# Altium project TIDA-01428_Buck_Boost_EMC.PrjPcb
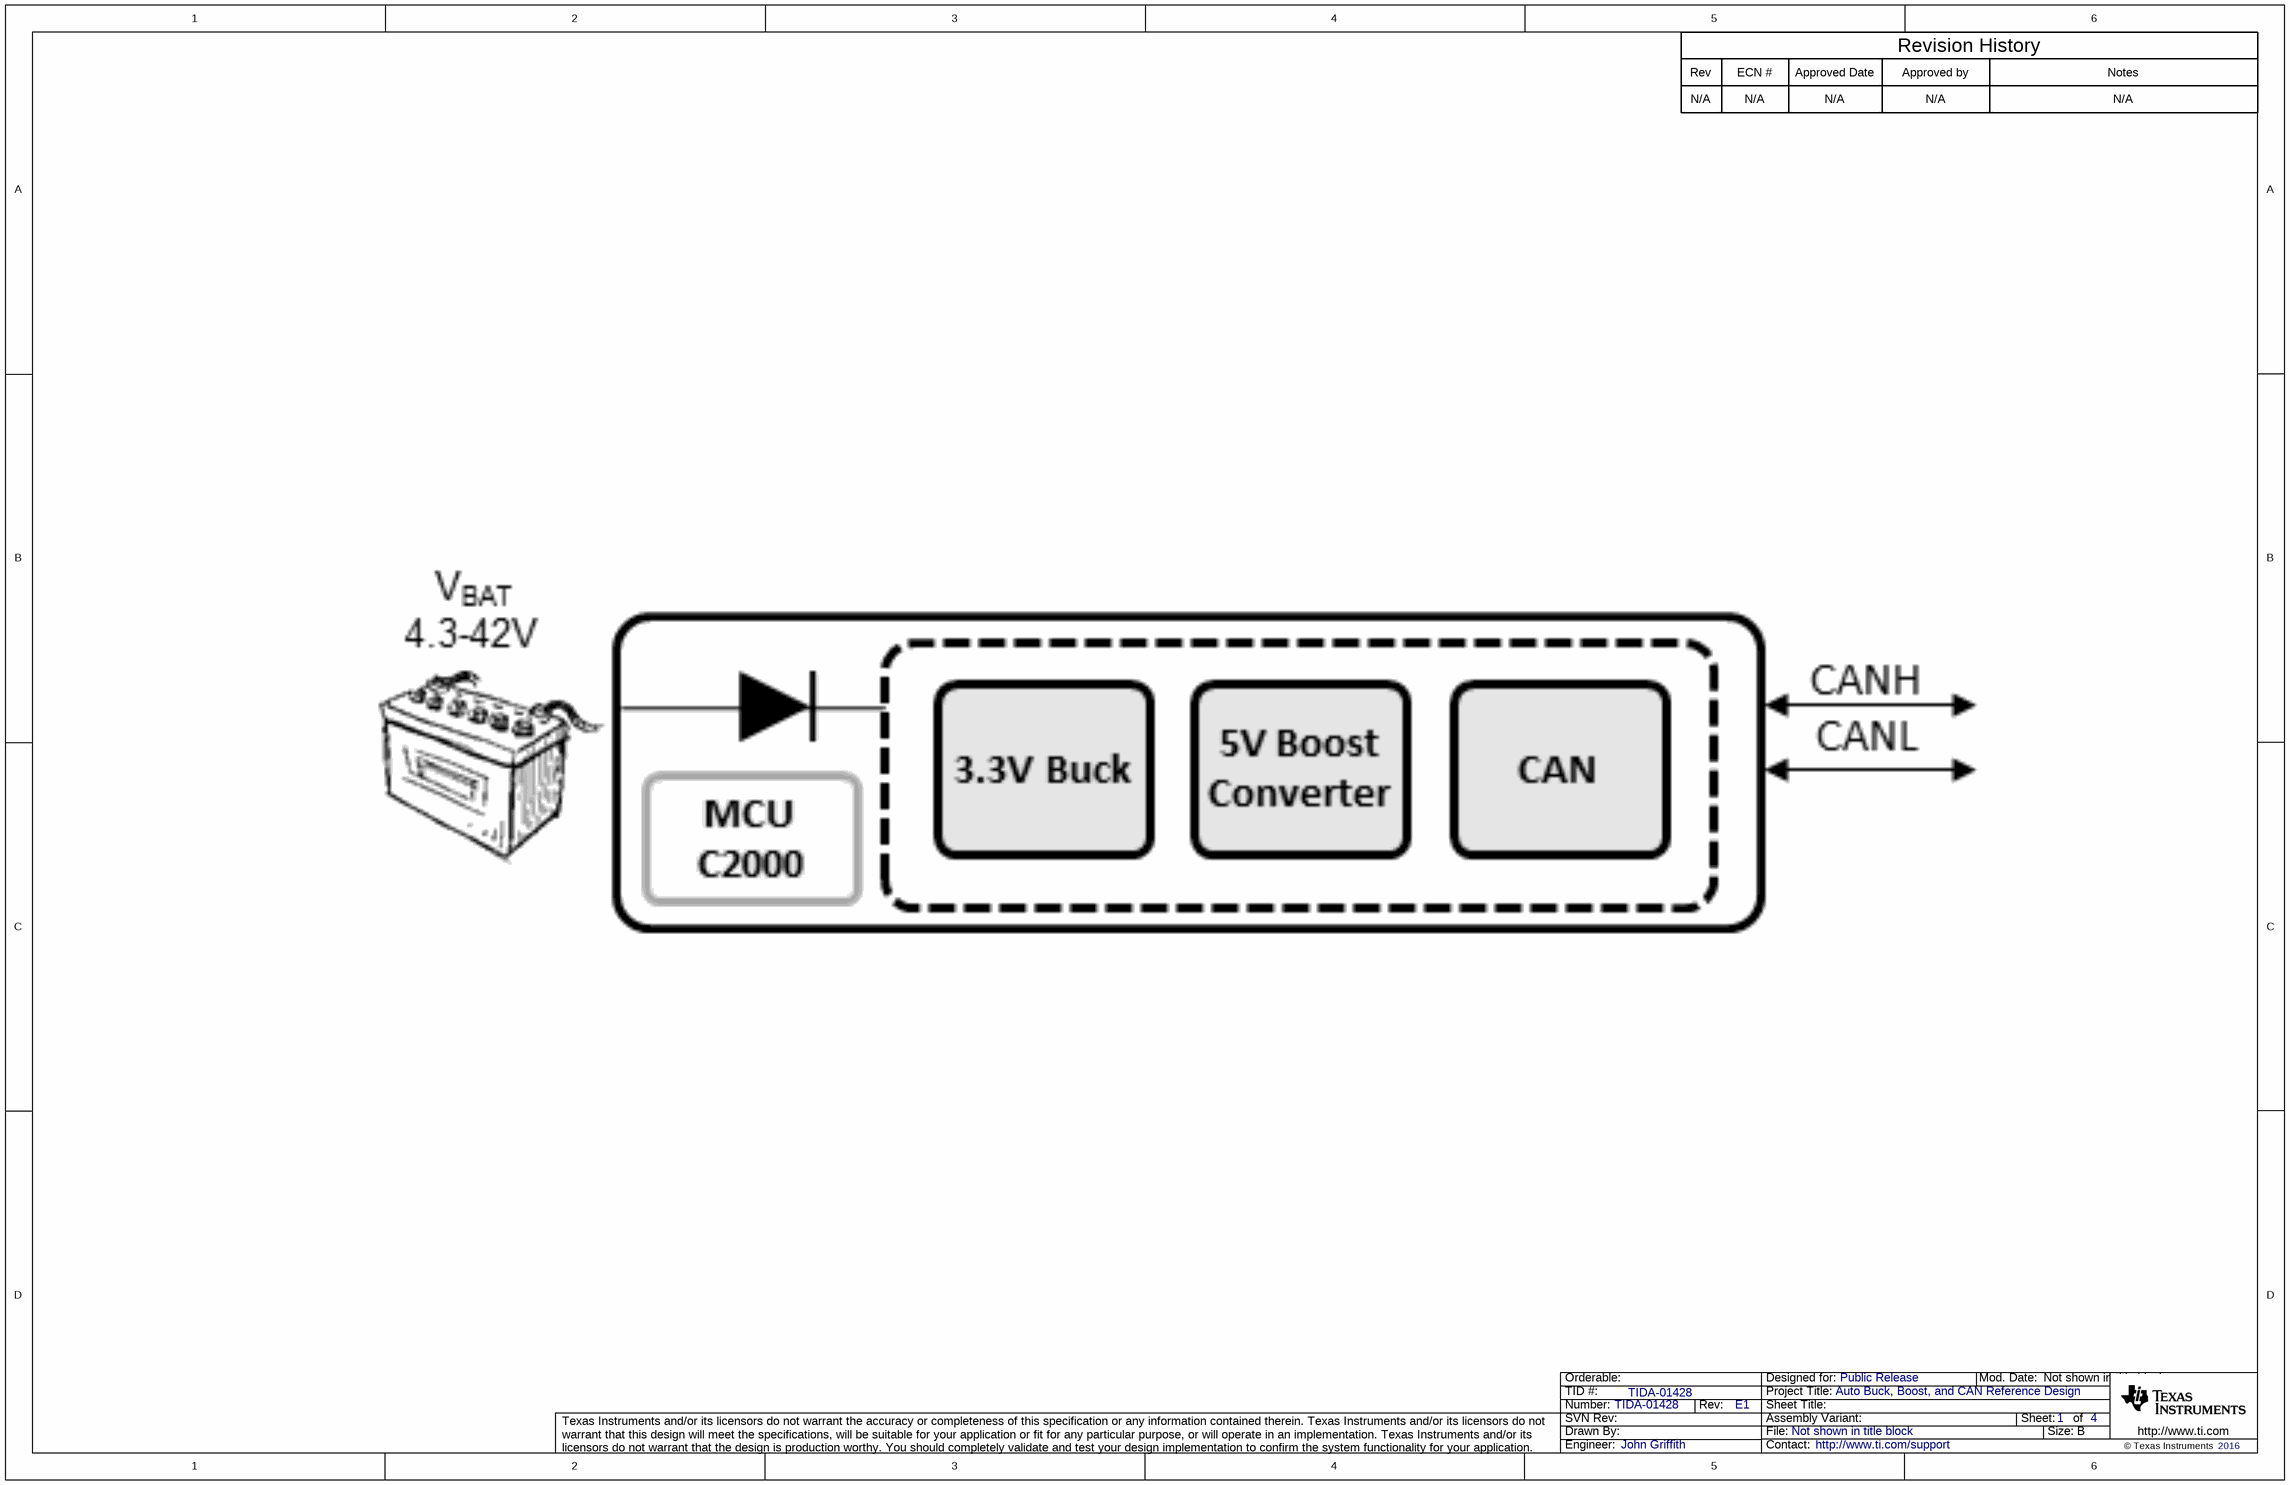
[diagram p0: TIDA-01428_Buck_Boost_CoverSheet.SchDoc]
CopyrightYear: 2016; PCB_Layout: John Griffith; PCB_Rev: E1; PRJ_Customer: Public Release; PRJ_Engineer: John Griffith; PRJ_Number: TIDA-01428; PRJ_Title: Auto Buck, Boost, and CAN Reference Design; SCH_Rev: E1; TechSupport: http://www.ti.com/support; TID: TIDA-01428
4 sheets, 128 parts. Net scope: global (net labels, ports and power ports of the same name join across sheets).
Board file: TIDA-01428_Buck_Boost_PCB.PcbDoc
Sheets:
  TIDA-01428_Buck_Boost_CoverSheet.SchDoc
  TIDA-01428_Buck_Boost_MCU.SchDoc
  TIDA-01428_Buck_Boost_Main.SchDoc
  TIDA-01428_Buck_Boost_Hardware.SchDoc

## Sheet TIDA-01428_Buck_Boost_CoverSheet.SchDoc
size 431 x 279 mm; Date: Not shown in title block; ApprovedBy: Not shown in title block; CheckedBy: Not shown in title block; Author: Not shown in title block; CompanyName: Not shown in title block; Engineer: Not shown in title block; Organization: Not shown in title block; Address1: Not shown in title block; Address2: Not shown in title block; Address3: Not shown in title block; Address4: Not shown in title block; DocumentNumber: 1; Revision: Use project parameter SCH_Rev; SheetNumber: 1; SheetTotal: 4; PageSetup: Record=PageOptions¦CenterHorizontal=True¦CenterVertical=True¦PrintScale=1.00¦XCorrection=1.00¦YCorrection=1.00¦PrintKind=0¦BorderSize=5000000¦LeftOffset=0¦BottomOffset=0¦Orientation=2¦PaperLength=1000¦PaperWidth=1000¦Scale=100¦PaperSource=15¦PrintQuality=600¦MediaType=1¦DitherType=10¦PaperKind=Letter¦PrintScaleMode=1

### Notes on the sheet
- Rev
- N/A
- ECN #
- Approved Date
- Approved by
- Revision History
- Notes

## Sheet TIDA-01428_Buck_Boost_MCU.SchDoc
size 431 x 279 mm; Date: Not shown in title block; ApprovedBy: Not shown in title block; CheckedBy: Not shown in title block; Author: Not shown in title block; CompanyName: Not shown in title block; Engineer: Not shown in title block; Organization: Not shown in title block; Address1: Not shown in title block; Address2: Not shown in title block; Address3: Not shown in title block; Address4: Not shown in title block; DocumentNumber: 2; Revision: Use project parameter SCH_Rev; SheetNumber: 2; SheetTotal: 4; PageSetup: Record=PageOptions¦CenterHorizontal=True¦CenterVertical=True¦PrintScale=1.00¦XCorrection=1.00¦YCorrection=1.00¦PrintKind=0¦BorderSize=5000000¦LeftOffset=0¦BottomOffset=0¦Orientation=2¦PaperLength=1000¦PaperWidth=1000¦Scale=100¦PaperSource=15¦PrintQuality=600¦MediaType=1¦DitherType=10¦PaperKind=Letter¦PrintScaleMode=1
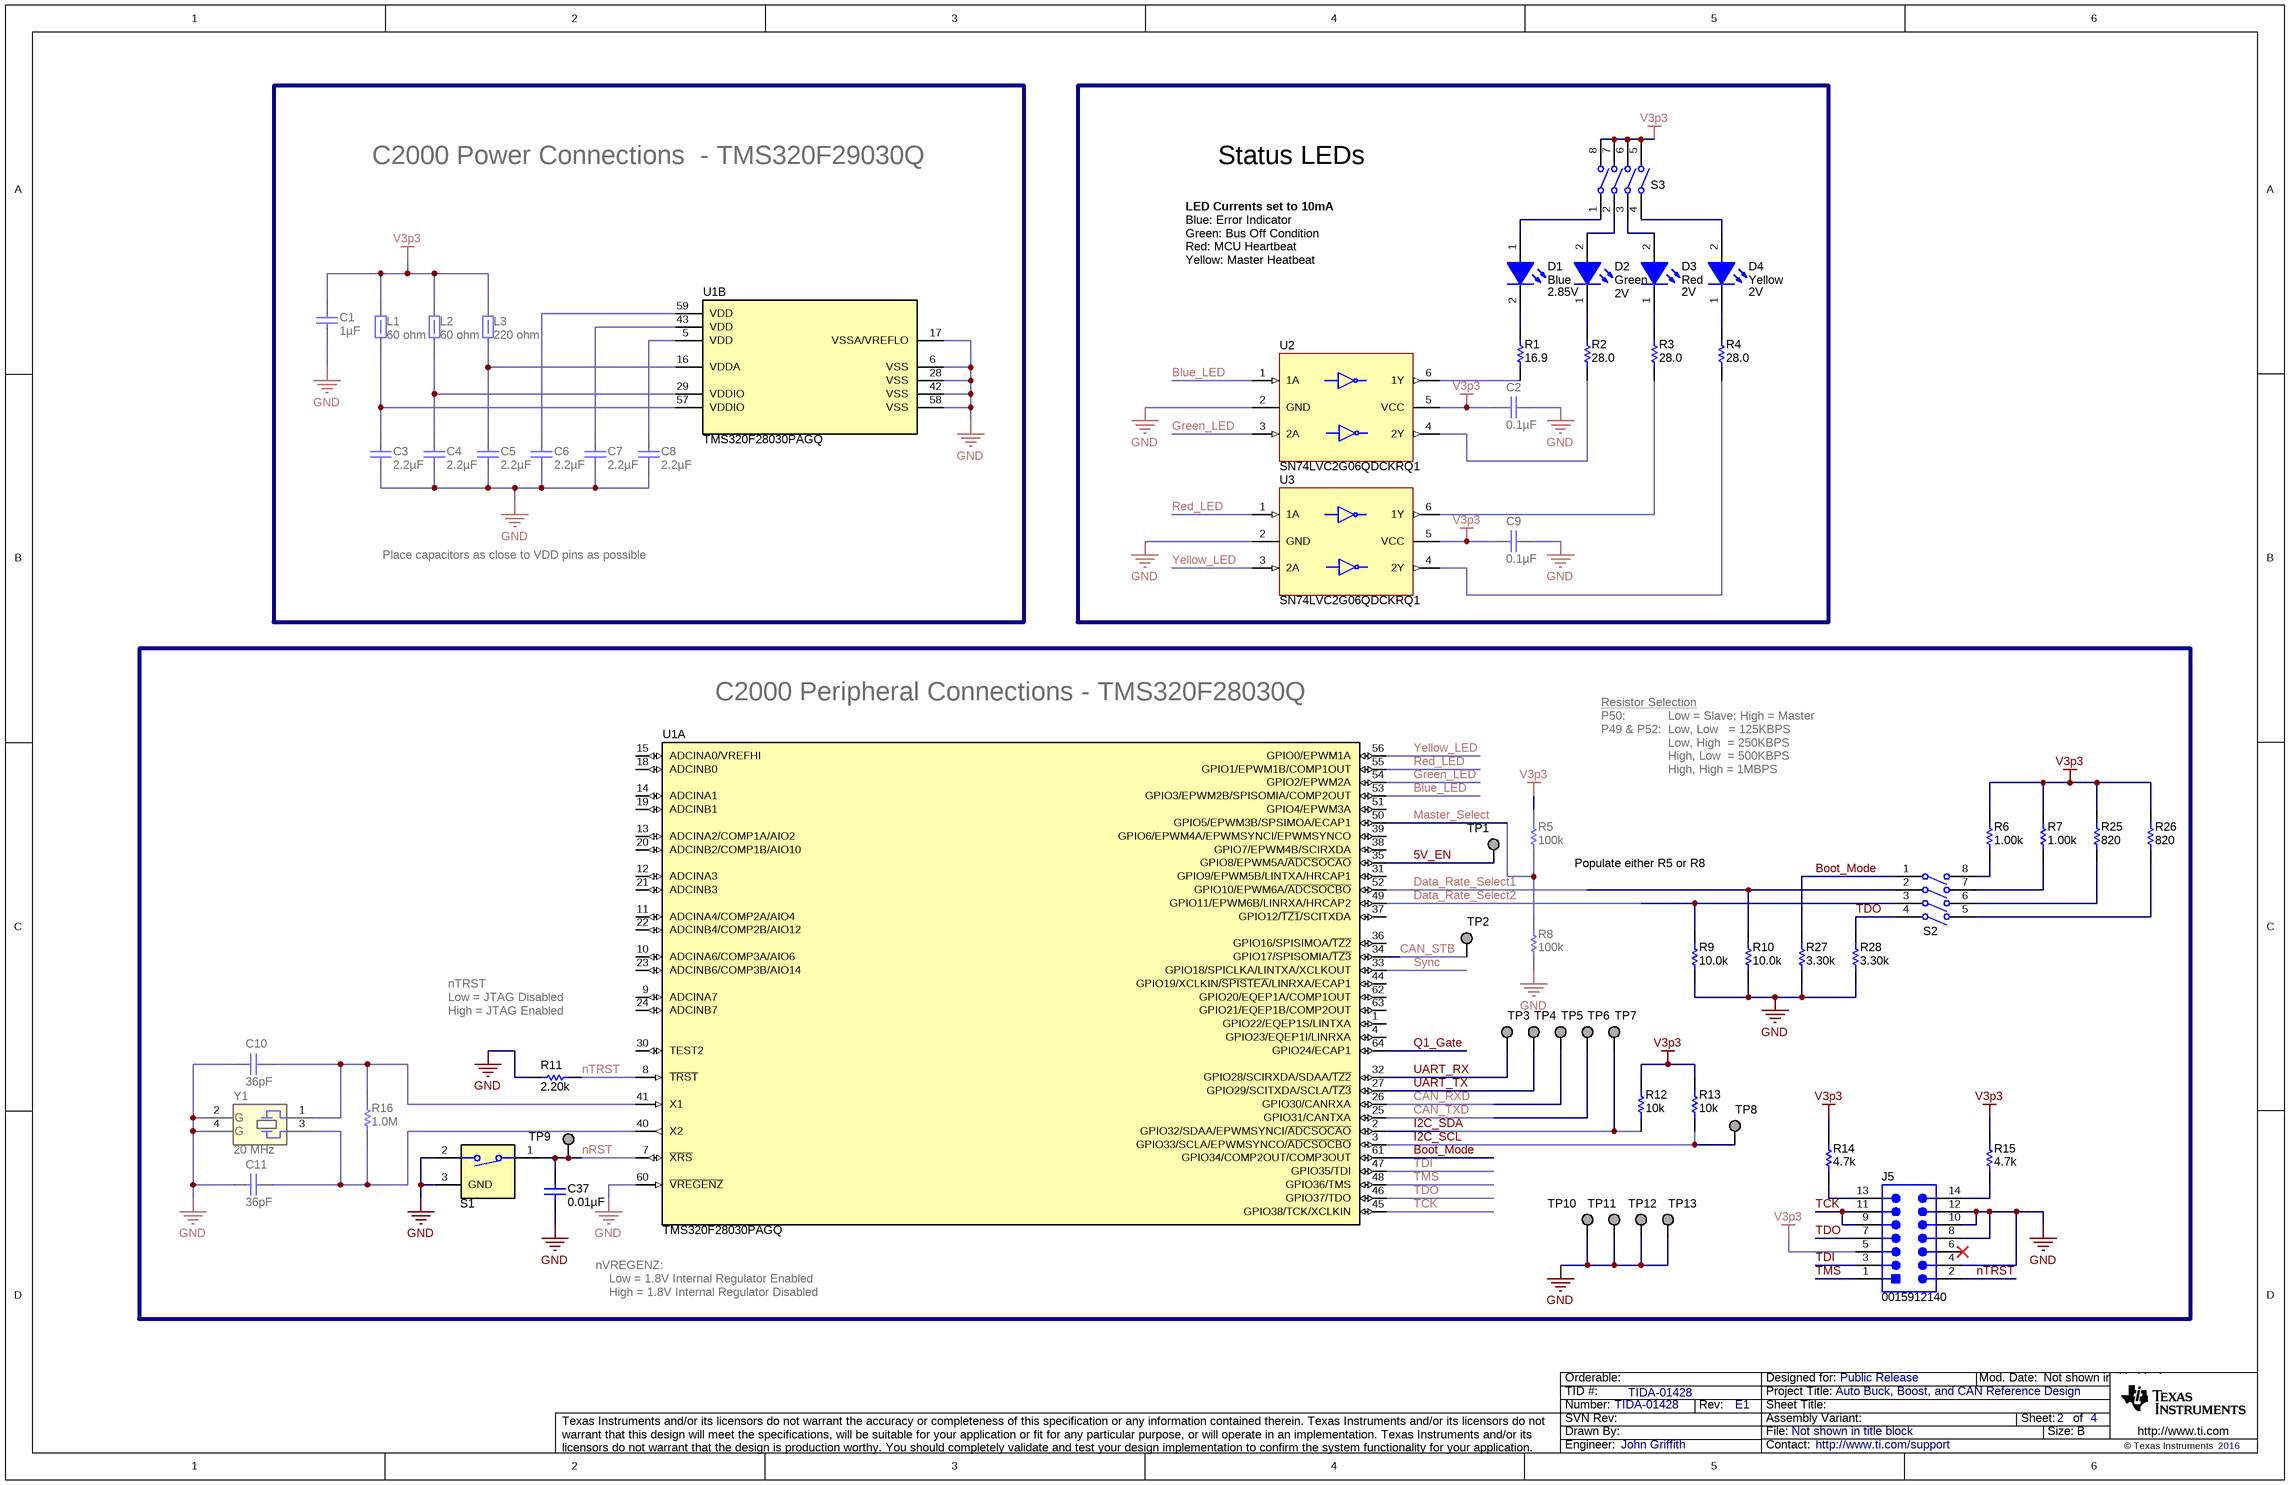
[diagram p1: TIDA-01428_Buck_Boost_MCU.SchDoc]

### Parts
C1  ValueDisplayed: 1µF  [0603S]  (hidden comment: C1608X5R1A105K080AC)
C2  ValueDisplayed: 0.1µF  [0603S]  (hidden comment: 06033C104JAT2A)
C3  ValueDisplayed: 2.2µF  [0603S]  (hidden comment: C0603C225K9PACTU)
C4  ValueDisplayed: 2.2µF  [0603S]  (hidden comment: C0603C225K9PACTU)
C5  ValueDisplayed: 2.2µF  [0603S]  (hidden comment: C0603C225K9PACTU)
C6  ValueDisplayed: 2.2µF  [0603S]  (hidden comment: C0603C225K9PACTU)
C7  ValueDisplayed: 2.2µF  [0603S]  (hidden comment: C0603C225K9PACTU)
C8  ValueDisplayed: 2.2µF  [0603S]  (hidden comment: C0603C225K9PACTU)
C9  ValueDisplayed: 0.1µF  [0603S]  (hidden comment: 06033C104JAT2A)
C10  ValueDisplayed: 36pF  [0402]  (hidden comment: GRM1555C1E360JA01D)
C11  ValueDisplayed: 36pF  [0402]  (hidden comment: GRM1555C1E360JA01D)
C37  ValueDisplayed: 0.01µF  [0603S]  (hidden comment: 06031C103JAT2A)
D1  value Blue  Value2: 2.85V  [LB Q39G_BLUE]  (hidden comment: LB Q39G-L2N2-35-1)
D2  value Green  Value2: 2V  [WL-SMCW_GREEN]  (hidden comment: 150060VS75000)
D3  value Red  Value2: 2V  [WL-SMCW_RED]  (hidden comment: 150060RS75000)
D4  value Yellow  Value2: 2V  [WL-SMCW_YELLOW]  (hidden comment: 150060YS75000)
J5  0015912140  [Molex_0015912140]
L1  ValueDisplayed: 60 ohm  [0603S]  (hidden comment: 742792602)
L2  ValueDisplayed: 60 ohm  [0603S]  (hidden comment: 742792602)
L3  ValueDisplayed: 220 ohm  [0805]  (hidden comment: BLM21PG221SN1D)
R1  ValueDisplayed: 16.9  [0603S]  (hidden comment: RC0603FR-0716R9L)
R2  ValueDisplayed: 28.0  [0603S]  (hidden comment: CRCW060328R0FKEA)
R3  ValueDisplayed: 28.0  [0603S]  (hidden comment: CRCW060328R0FKEA)
R4  ValueDisplayed: 28.0  [0603S]  (hidden comment: CRCW060328R0FKEA)
R5  ValueDisplayed: 100k  [0603S]  (hidden comment: CRCW0603100KFKEA)
R6  ValueDisplayed: 1.00k  [0603S]  (hidden comment: CRCW06031K00FKEA)
R7  ValueDisplayed: 1.00k  [0603S]  (hidden comment: CRCW06031K00FKEA)
R8  ValueDisplayed: 100k  [0603S]  (hidden comment: CRCW0603100KFKEA)
R9  ValueDisplayed: 10.0k  [0603S]  (hidden comment: CRCW060310K0FKEA)
R10  ValueDisplayed: 10.0k  [0603S]  (hidden comment: CRCW060310K0FKEA)
R11  ValueDisplayed: 2.20k  [0603S]  (hidden comment: RC0603FR-072K2L)
R12  ValueDisplayed: 10k  [0603S]  (hidden comment: CRCW060310K0JNEA)
R13  ValueDisplayed: 10k  [0603S]  (hidden comment: CRCW060310K0JNEA)
R14  ValueDisplayed: 4.7k  [0603S]  (hidden comment: CRCW06034K70JNEA)
R15  ValueDisplayed: 4.7k  [0603S]  (hidden comment: CRCW06034K70JNEA)
R16  ValueDisplayed: 1.0M  [0402]  (hidden comment: CRCW04021M00JNED)
R25  ValueDisplayed: 820  [0603S]  (hidden comment: RC0603FR-07820RL)
R26  ValueDisplayed: 820  [0603S]  (hidden comment: RC0603FR-07820RL)
R27  ValueDisplayed: 3.30k  [0603S]  (hidden comment: RC0603FR-073K3L)
R28  ValueDisplayed: 3.30k  [0603S]  (hidden comment: RC0603FR-073K3L)
S1  B3U-1100P  [SW_B3U-1100P]  (value not drawn)
S2  1571983-5  [SW_1571983-5]  (value not drawn)
S3  1571983-5  [SW_1571983-5]  (value not drawn)
TP1  PAD_1MM_SQUARE  [PAD_1MM_SQUARE]  (value not drawn)  (no BOM)
TP2  PAD_1MM_SQUARE  [PAD_1MM_SQUARE]  (value not drawn)  (no BOM)
TP3  PAD_1MM_SQUARE  [PAD_1MM_SQUARE]  (value not drawn)  (no BOM)
TP4  PAD_1MM_SQUARE  [PAD_1MM_SQUARE]  (value not drawn)  (no BOM)
TP5  PAD_1MM_SQUARE  [PAD_1MM_SQUARE]  (value not drawn)  (no BOM)
TP6  PAD_1MM_SQUARE  [PAD_1MM_SQUARE]  (value not drawn)  (no BOM)
TP7  PAD_1MM_SQUARE  [PAD_1MM_SQUARE]  (value not drawn)  (no BOM)
TP8  PAD_1MM_SQUARE  [PAD_1MM_SQUARE]  (value not drawn)  (no BOM)
TP9  PAD_1MM_SQUARE  [PAD_1MM_SQUARE]  (value not drawn)  (no BOM)
TP10  PAD_1MM_SQUARE  [PAD_1MM_SQUARE]  (value not drawn)  (no BOM)
TP11  PAD_1MM_SQUARE  [PAD_1MM_SQUARE]  (value not drawn)  (no BOM)
TP12  PAD_1MM_SQUARE  [PAD_1MM_SQUARE]  (value not drawn)  (no BOM)
TP13  PAD_1MM_SQUARE  [PAD_1MM_SQUARE]  (value not drawn)  (no BOM)
U1  TMS320F28030PAGQ  [PAG0064A_N]  (parts A,B of 2)
U2  SN74LVC2G06QDCKRQ1  [DCK0006A_N]
U3  SN74LVC2G06QDCKRQ1  [DCK0006A_N]
Y1  Frequency: 20 MHz  [ABRACON_ABM3B]  (hidden comment: ABM3B-20.000MHZ-10-1-U-T)

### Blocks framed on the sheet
Place capacitors as close to VDD pins as possible: C1 C3-C8 L1-L3 U1

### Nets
GND: C1.2 C2.2 C3.2 C4.2 C5.2 C6.2 C7.2 C8.2 C9.2 C10.2 C11.2 C37.2 J5.4 J5.8 J5.10 J5.12 R8.1 R9.1 R10.1 R11.1 R27.1 R28.1 S1.2 S1.3(GND) TP10.1 TP11.1 TP12.1 TP13.1 U1.6(VSS) U1.17(VSSA/VREFLO) U1.28(VSS) U1.42(VSS) U1.58(VSS) U1.60(~{VREGENZ}) U2.2(GND) U3.2(GND) Y1.2(GND) Y1.4(GND)
V3p3: C1.1 C2.1 C9.1 J5.5 L1.2 L2.2 L3.2 R5.2 R6.2 R7.2 R12.2 R13.2 R14.2 R15.2 R25.2 R26.2 S3.5(B4) S3.6(B3) S3.7(B2) S3.8(B1) U2.5(VCC) U3.5(VCC)
5V_EN: TP1.1 U1.35(GPIO8/EPWM5A/~{ADCSOCAO})
Blue_LED: U1.53(GPIO3/EPWM2B/SPISOMIA/COMP2OUT) U2.1(1A)
Boot_Mode: R27.2 S2.1(A1) U1.61(GPIO34/COMP2OUT/COMP3OUT)
CAN_RXD: TP5.1 U1.26(GPIO30/CANRXA)
CAN_STB: TP2.1 U1.34(GPIO17/SPISOMIA/~{TZ3})
CAN_TXD: TP6.1 U1.25(GPIO31/CANTXA)
Data_Rate_Select1: R10.2 S2.2(A2) U1.52(GPIO10/EPWM6A/~{ADCSOCBO})
Data_Rate_Select2: R9.2 S2.3(A3) U1.49(GPIO11/EPWM6B/LINRXA/HRCAP2)
Green_LED: U1.54(GPIO2/EPWM2A) U2.3(2A)
I2C_SCL: R13.1 TP8.1 U1.3(GPIO33/SCLA/EPWMSYNCO/~{ADCSOCBO})
I2C_SDA: R12.1 TP7.1 U1.2(GPIO32/SDAA/EPWMSYNCI/~{ADCSOCAO})
Master_Select: R5.1 R8.2 U1.50(GPIO5/EPWM3B/SPSIMOA/ECAP1)
nRST: C37.1 S1.1 TP9.1 U1.7(~{XRS})
nTRST: J5.2 R11.2 U1.8(~{TRST})
Q1_Gate: U1.64(GPIO24/ECAP1)
Red_LED: U1.55(GPIO1/EPWM1B/COMP1OUT) U3.1(1A)
Sync: U1.33(GPIO18/SPICLKA/LINTXA/XCLKOUT)
TCK: J5.9 J5.11 U1.45(GPIO38/TCK/XCLKIN)
TDI: J5.3 U1.47(GPIO35/TDI)
TDO: J5.7 R28.2 S2.4(A4) U1.46(GPIO37/TDO)
TMS: J5.1 U1.48(GPIO36/TMS)
UART_RX: TP3.1 U1.32(GPIO28/SCIRXDA/SDAA/~{TZ2})
UART_TX: TP4.1 U1.27(GPIO29/SCITXDA/SCLA/~{TZ3})
Yellow_LED: U1.56(GPIO0/EPWM1A) U3.3(2A)
NetC3_1: C3.1 L1.1 U1.57(VDDIO)
NetC4_1: C4.1 L2.1 U1.29(VDDIO)
NetC5_1: C5.1 L3.1 U1.16(VDDA)
NetC6_1: C6.1 U1.59(VDD)
NetC7_1: C7.1 U1.43(VDD)
NetC8_1: C8.1 U1.5(VDD)
NetC10_1: C10.1 R16.2 U1.41(X1) Y1.1
NetC11_1: C11.1 R16.1 U1.40(X2) Y1.3
NetD1_1: D1.1(A) S3.1(A1)
NetD1_2: D1.2(K) R1.2
NetD2_1: D2.1(K) R2.2
NetD2_2: D2.2(A) S3.2(A2)
NetD3_1: D3.1(K) R3.2
NetD3_2: D3.2(A) S3.3(A3)
NetD4_1: D4.1(K) R4.2
NetD4_2: D4.2(A) S3.4(A4)
NetJ5_13: J5.13 R14.1
NetJ5_14: J5.14 R15.1
NetR1_1: R1.1 U2.6(1Y)
NetR2_1: R2.1 U2.4(2Y)
NetR3_1: R3.1 U3.6(1Y)
NetR4_1: R4.1 U3.4(2Y)
NetR6_1: R6.1 S2.8(B1)
NetR7_1: R7.1 S2.7(B2)
NetR25_1: R25.1 S2.6(B3)
NetR26_1: R26.1 S2.5(B4)

Not connected (* = marked no-connect by the designer): J5 6*; U1 1(GPIO22/EQEP1S/LINTXA) 4(GPIO23/EQEP1I/LINRXA) 9(ADCINA7) 10(ADCINA6/COMP3A/AIO6) 11(ADCINA4/COMP2A/AIO4) 12(ADCINA3) 13(ADCINA2/COMP1A/AIO2) 14(ADCINA1) 15(ADCINA0/VREFHI) 18(ADCINB0) 19(ADCINB1) 20(ADCINB2/COMP1B/AIO10) 21(ADCINB3) 22(ADCINB4/COMP2B/AIO12) 23(ADCINB6/COMP3B/AIO14) 24(ADCINB7) 30(TEST2) 31(GPIO9/EPWM5B/LINTXA/HRCAP1) 36(GPIO16/SPISIMOA/~{TZ2}) 37(GPIO12/~{TZ1}/SCITXDA) 38(GPIO7/EPWM4B/SCIRXDA) 39(GPIO6/EPWM4A/EPWMSYNCI/EPWMSYNCO) 44(GPIO19/XCLKIN/~{SPISTEA}/LINRXA/ECAP1) 51(GPIO4/EPWM3A) 62(GPIO20/EQEP1A/COMP1OUT) 63(GPIO21/EQEP1B/COMP2OUT)

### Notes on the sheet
- C2000 Power Connections  - TMS320F29030Q
- Status LEDs
- Blue: Error Indicator
- Green: Bus Off Condition
- LED Currents set to 10mA
- Red: MCU Heartbeat
- Yellow: Master Heatbeat
- Mode Selection DIP Switches
- Resistor Selection
- (near U1) C2000 Peripheral Connections - TMS320F28030Q
- P49 & P52:
- P50:
- Low = Slave; High = Master
- Low, Low   = 125KBPS
- Low, High  = 250KBPS
- High, Low  = 500KBPS
- High, High = 1MBPS
- (near R5) Populate either R5 or R8
- Low = JTAG Disabled
- High = JTAG Enabled
- nTRST
- JTAG Interface
- nVREGENZ:
- Low = 1.8V Internal Regulator Enabled
- High = 1.8V Internal Regulator Disabled

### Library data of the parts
C1 = C1608X5R1A105K080AC: CAP, CERM, 1 µF, 10 V, +/- 10%, X5R, 0603; Manufacturer: TDK; Polarized: N; CompType: Capacitor; Value: 1uF; U/M: EA; Cap_F: 0.000001; Tolerance_%: 10; Value1: Unknown; Value2: 10V; TaMin_C: -55; TaMax_C: 85; Cap_Case: 0603; SizeArea_mm2: 1.28; SizeAreaWB_mm2: 4.68; SizeX_mm: 1.6; SizeY_mm: 0.8; SizeZ_mm: 1; AEC Category: Q200
C2 C9 = 06033C104JAT2A: CAP, CERM, 0.1 µF, 25 V, +/- 5%, X7R, 0603; Manufacturer: AVX; Polarized: N; CompType: Capacitor; Value: 0.1uF; U/M: EA; Cap_F: 0.0000001; Tolerance_%: 5; ESR_ohm: 0.05; Value1: 0.05 ohm; VDC_V: 25; Value2: 25V; TaMin_C: -55; TaMax_C: 125; Cap_Case: 0603; SizeArea_mm2: 1.28; SizeAreaWB_mm2: 4.68; SizeX_mm: 1.6; SizeY_mm: 0.8; SizeZ_mm: 1; AEC Category: Q200
C3-C8 = C0603C225K9PACTU: CAP, CERM, 2.2 µF, 6.3 V, +/- 10%, X5R, 0603; Manufacturer: Kemet; Polarized: N; CompType: Capacitor; Value: 2.2uF; U/M: EA; Cap_F: 0.0000022; Tolerance_%: 10; Value1: Unknown; VDC_V: 6.3; Value2: 6.3V; TaMin_C: -55; TaMax_C: 85; Cap_Case: 0603; SizeArea_mm2: 1.28; SizeAreaWB_mm2: 4.68; SizeX_mm: 1.6; SizeY_mm: 0.8; SizeZ_mm: 1; AEC Category: Q200
C10 C11 = GRM1555C1E360JA01D: CAP, CERM, 36 pF, 25 V, +/- 5%, C0G/NP0, 0402; Manufacturer: MuRata; Polarized: N; CompType: Capacitor; Value: 36pF; U/M: EA; Cap_F: 0.000000000036; Tolerance_%: 5; Value1: Unknown; VDC_V: 25; Value2: 25V; TaMin_C: -55; TaMax_C: 125; SizeArea_mm2: 0.5; SizeAreaWB_mm2: 3; SizeX_mm: 1; SizeZ_mm: 0.6; AEC Category: Q200
C37 = 06031C103JAT2A: CAP, CERM, 0.01 µF, 100 V, +/- 5%, X7R, 0603; Manufacturer: AVX; Polarized: N; CompType: Capacitor; Value: 0.01uF; U/M: EA; Cap_F: 0.00000001; Tolerance_%: 5; ESR_ohm: 0.098; Value1: 0.098 ohm; VDC_V: 100; Value2: 100V; TaMin_C: -55; TaMax_C: 125; Cap_Case: 0603; SizeArea_mm2: 1.28; SizeAreaWB_mm2: 4.68; SizeX_mm: 1.6; SizeY_mm: 0.8; SizeZ_mm: 1; AEC Category: Q200
D1 = LB Q39G-L2N2-35-1: LED, Blue, SMD; Manufacturer: OSRAM; Vf_V: 2.85; Io_A: 0.15; Tjmax_C: 95; Value1: W; U/M: EA
D2 = 150060VS75000: LED, Green, SMD; Manufacturer: Wurth Elektronik; Type: AlInGaP; Vf_V: 2; Io_A: 0.02; Value1: W; U/M: EA
D3 = 150060RS75000: LED, Red, SMD; Manufacturer: Wurth Elektronik; Type: AlInGaP; Vf_V: 2; Io_A: 0.03; Vr_V: 5; Tjmax_C: 85; Power_TotalModule: 0.072; Value1: 0.072W; Angle: 140; U/M: EA
D4 = 150060YS75000: LED, Yellow, SMD; Manufacturer: Wurth Elektronik; Type: AlInGaP; Vf_V: 2; Io_A: 0.02; Value1: W; U/M: EA
J5 = 0015912140: Header, 100mil, 7x2, SMT; Manufacturer: Molex; SymbolCreator: a0412235
L1 L2 = 742792602: Ferrite Bead, 60 ohm @ 100 MHz, 3 A, 0603; Manufacturer: Wurth Elektronik; Value: 60 ohm; Imax_A: 3; DCR_ohm: 0.04; Value1: 0.04 ohm; Value2: 3A; SizeAreaWB_mm2: 4.68; SizeArea_mm2: 1.28; SizeX_mm: 1.6; SizeY_mm: 0.8; SizeZ_mm: 1; ZTyp@100MHz_Ohm: 60; Ztyp@1GHz_Ohm: 110.436
L3 = BLM21PG221SN1D: Ferrite Bead, 220 ohm @ 100 MHz, 2 A, 0805; Manufacturer: MuRata; Value: 220 ohm; Imax_A: 2; DCR_ohm: 0.045; Value1: 0.045 ohm; Value2: 2A; SizeAreaWB_mm2: 6.75; SizeArea_mm2: 2.5; SizeY_mm: 1.25; SizeZ_mm: 1.45; ZTyp@100MHz_Ohm: 220
R1 = RC0603FR-0716R9L: RES, 16.9, 1%, 0.1 W, 0603; Manufacturer: Yageo America; CompType: Resistor; Value: 16.9; Value_Code: 16R9; Tolerance_%: 1; Power_W: 0.1; Value2: 0.1W; VDC_V: 150; TempCo: 200 ppm/C; SizeArea_mm2: 1.28; SizeX_mm: 1.6; SizeY_mm: 0.8; EIA_Code: E96; U/M: EA; AEC Category: Q200
R2-R4 = CRCW060328R0FKEA: RES, 28.0, 1%, 0.1 W, 0603; Manufacturer: Vishay-Dale; CompType: Resistor; Value: 28.0; Res_ohm: 28; Value_Code: 28R0; Tolerance_%: 1; Power_W: 0.1; Value2: 0.1W; VDC_V: 75; TempCo: 100 ppm/C; SizeArea_mm2: 1.28; SizeX_mm: 1.6; SizeY_mm: 0.8; EIA_Code: E96; U/M: EA; AEC Category: Q200
R5 R8 = CRCW0603100KFKEA: RES, 100 k, 1%, 0.1 W, 0603; Manufacturer: Vishay-Dale; CompType: Resistor; Value: 100k; Res_ohm: 100000; Tolerance_%: 1; Power_W: 0.1; Value2: 0.1W; VDC_V: 75; TempCo: 100 ppm/C; SizeArea_mm2: 1.28; SizeX_mm: 1.6; SizeY_mm: 0.8; EIA_Code: E96; U/M: EA; AEC Category: Q200
R6 R7 = CRCW06031K00FKEA: RES, 1.00 k, 1%, 0.1 W, 0603; Manufacturer: Vishay-Dale; CompType: Resistor; Value: 1.00k; Res_ohm: 1000; Value_Code: 1k00; Tolerance_%: 1; Power_W: 0.1; Value2: 0.1W; VDC_V: 75; TempCo: 100 ppm/C; SizeArea_mm2: 1.28; SizeX_mm: 1.6; SizeY_mm: 0.8; EIA_Code: E96; U/M: EA; AEC Category: Q200
R9 R10 = CRCW060310K0FKEA: RES, 10.0 k, 1%, 0.1 W, 0603; Manufacturer: Vishay-Dale; CompType: Resistor; Value: 10.0k; Res_ohm: 10000; Value_Code: 10k0; Tolerance_%: 1; Power_W: 0.1; Value2: 0.1W; VDC_V: 75; TempCo: 100 ppm/C; SizeArea_mm2: 1.28; SizeX_mm: 1.6; SizeY_mm: 0.8; EIA_Code: E96; U/M: EA; AEC Category: Q200
R11 = RC0603FR-072K2L: RES, 2.20 k, 1%, 0.1 W, 0603; Manufacturer: Yageo America; CompType: Resistor; Value: 2.20k; Res_ohm: 2200; Value_Code: 2k20; Tolerance_%: 1; Power_W: 0.1; Value2: 0.1W; VDC_V: 150; TempCo: 200 ppm/C; SizeArea_mm2: 1.28; SizeX_mm: 1.6; SizeY_mm: 0.8; U/M: EA; AEC Category: Q200
R12 R13 = CRCW060310K0JNEA: RES, 10 k, 5%, 0.1 W, 0603; Manufacturer: Vishay-Dale; CompType: Resistor; Value: 10k; Res_ohm: 10000; Value_Code: 10k0; Tolerance_%: 5; Power_W: 0.1; Value2: 0.1W; VDC_V: 75; TempCo: 200 ppm/C; SizeArea_mm2: 1.28; SizeX_mm: 1.6; SizeY_mm: 0.8; SizeZ_mm: 1; EIA_Code: E24; U/M: EA; AEC Category: Q200
R14 R15 = CRCW06034K70JNEA: RES, 4.7 k, 5%, 0.1 W, 0603; Manufacturer: Vishay-Dale; CompType: Resistor; Value: 4.7k; Res_ohm: 4700; Value_Code: 4k70; Tolerance_%: 5; Power_W: 0.1; Value2: 0.1W; VDC_V: 75; TempCo: 200 ppm/C; SizeArea_mm2: 1.28; SizeX_mm: 1.6; SizeY_mm: 0.8; SizeZ_mm: 1; EIA_Code: E24; U/M: EA; AEC Category: Q200
R16 = CRCW04021M00JNED: RES, 1.0 M, 5%, 0.063 W, 0402; Manufacturer: Vishay-Dale; CompType: Resistor; Value: 1.0Meg; Res_ohm: 1000000; Value_Code: 1M00; Tolerance_%: 5; Power_W: 0.063; Value2: 0.063W; VDC_V: 50; TempCo: 200 ppm/C; SizeArea_mm2: 0.5; SizeX_mm: 1; SizeZ_mm: 0.6; EIA_Code: E24; U/M: EA; AEC Category: Q200
R25 R26 = RC0603FR-07820RL: RES, 820, 1%, 0.1 W, 0603; Manufacturer: Yageo America; CompType: Resistor; Value: 820; Value_Code: 820R; Tolerance_%: 1; Power_W: 0.1; Value2: 0.1W; VDC_V: 150; TempCo: 200 ppm/C; SizeArea_mm2: 1.28; SizeX_mm: 1.6; SizeY_mm: 0.8; U/M: EA; AEC Category: Q200
R27 R28 = RC0603FR-073K3L: RES, 3.30 k, 1%, 0.1 W, 0603; Manufacturer: Yageo America; CompType: Resistor; Value: 3.30k; Res_ohm: 3300; Value_Code: 3k30; Tolerance_%: 1; Power_W: 0.1; Value2: 0.1W; VDC_V: 150; TempCo: 200 ppm/C; SizeArea_mm2: 1.28; SizeX_mm: 1.6; SizeY_mm: 0.8; U/M: EA; AEC Category: Q200
S1 = B3U-1100P: Switch, SPST-NO, Off-Mom, 12 V, SMD; Manufacturer: Omron Electronic Components; SymbolCreator: Altium; VDC_V: 12; PositionCount: 1; CurrentRating_mA: 50
S2 S3 = 1571983-5: Switch, SPST, 4 Pos, Top Actuated, SMD; Manufacturer: TE Connectivity; SymbolCreator: a0412235; VDC_V: 24; PositionCount: 4; CurrentRating_mA: 25
TP1-TP13 = PAD_1MM_SQUARE: 1.0x1.0mm pad, square, SMD; Manufacturer: Any
U1 = TMS320F28030PAGQ: Piccolo Microcontroller, PAG0064A (TQFP-64); Manufacturer: Texas Instruments; SymbolCreator: a0412235; SizeArea_mm2: 144; SizeAreaWB_mm2: 196; SizeX_mm: 12; SizeZ_mm: 1.2; CompType: IC; U/M: EA
U2 U3 = SN74LVC2G06QDCKRQ1: Dual Inverter Buffer/Driver with Open-Drain Output, DCK0006A (SOT-6); Manufacturer: Texas Instruments; SymbolCreator: x0208326; SizeArea_mm2: 4.2; SizeAreaWB_mm2: 9.3; SizeX_mm: 2.1; SizeY_mm: 2; SizeZ_mm: 1.1; CompType: IC; U/M: EA
Y1 = ABM3B-20.000MHZ-10-1-U-T: Crystal, 20 MHz, 10 pF, SMD; Manufacturer: Abracon Corporation; SymbolCreator: a0412235; U/M: EA; TaMin_C: -10; TaMax_C: 60; Frequency Stability: ±10ppm

## Sheet TIDA-01428_Buck_Boost_Main.SchDoc
size 431 x 279 mm; Date: Not shown in title block; ApprovedBy: Not shown in title block; CheckedBy: Not shown in title block; Author: Not shown in title block; CompanyName: Not shown in title block; Engineer: Not shown in title block; Organization: Not shown in title block; Address1: Not shown in title block; Address2: Not shown in title block; Address3: Not shown in title block; Address4: Not shown in title block; DocumentNumber: 3; Revision: Use project parameter SCH_Rev; SheetNumber: 3; SheetTotal: 4; PageSetup: Record=PageOptions¦CenterHorizontal=True¦CenterVertical=True¦PrintScale=1.00¦XCorrection=1.00¦YCorrection=1.00¦PrintKind=0¦BorderSize=5000000¦LeftOffset=0¦BottomOffset=0¦Orientation=2¦PaperLength=1000¦PaperWidth=1000¦Scale=100¦PaperSource=15¦PrintQuality=600¦MediaType=1¦DitherType=10¦PaperKind=Letter¦PrintScaleMode=1
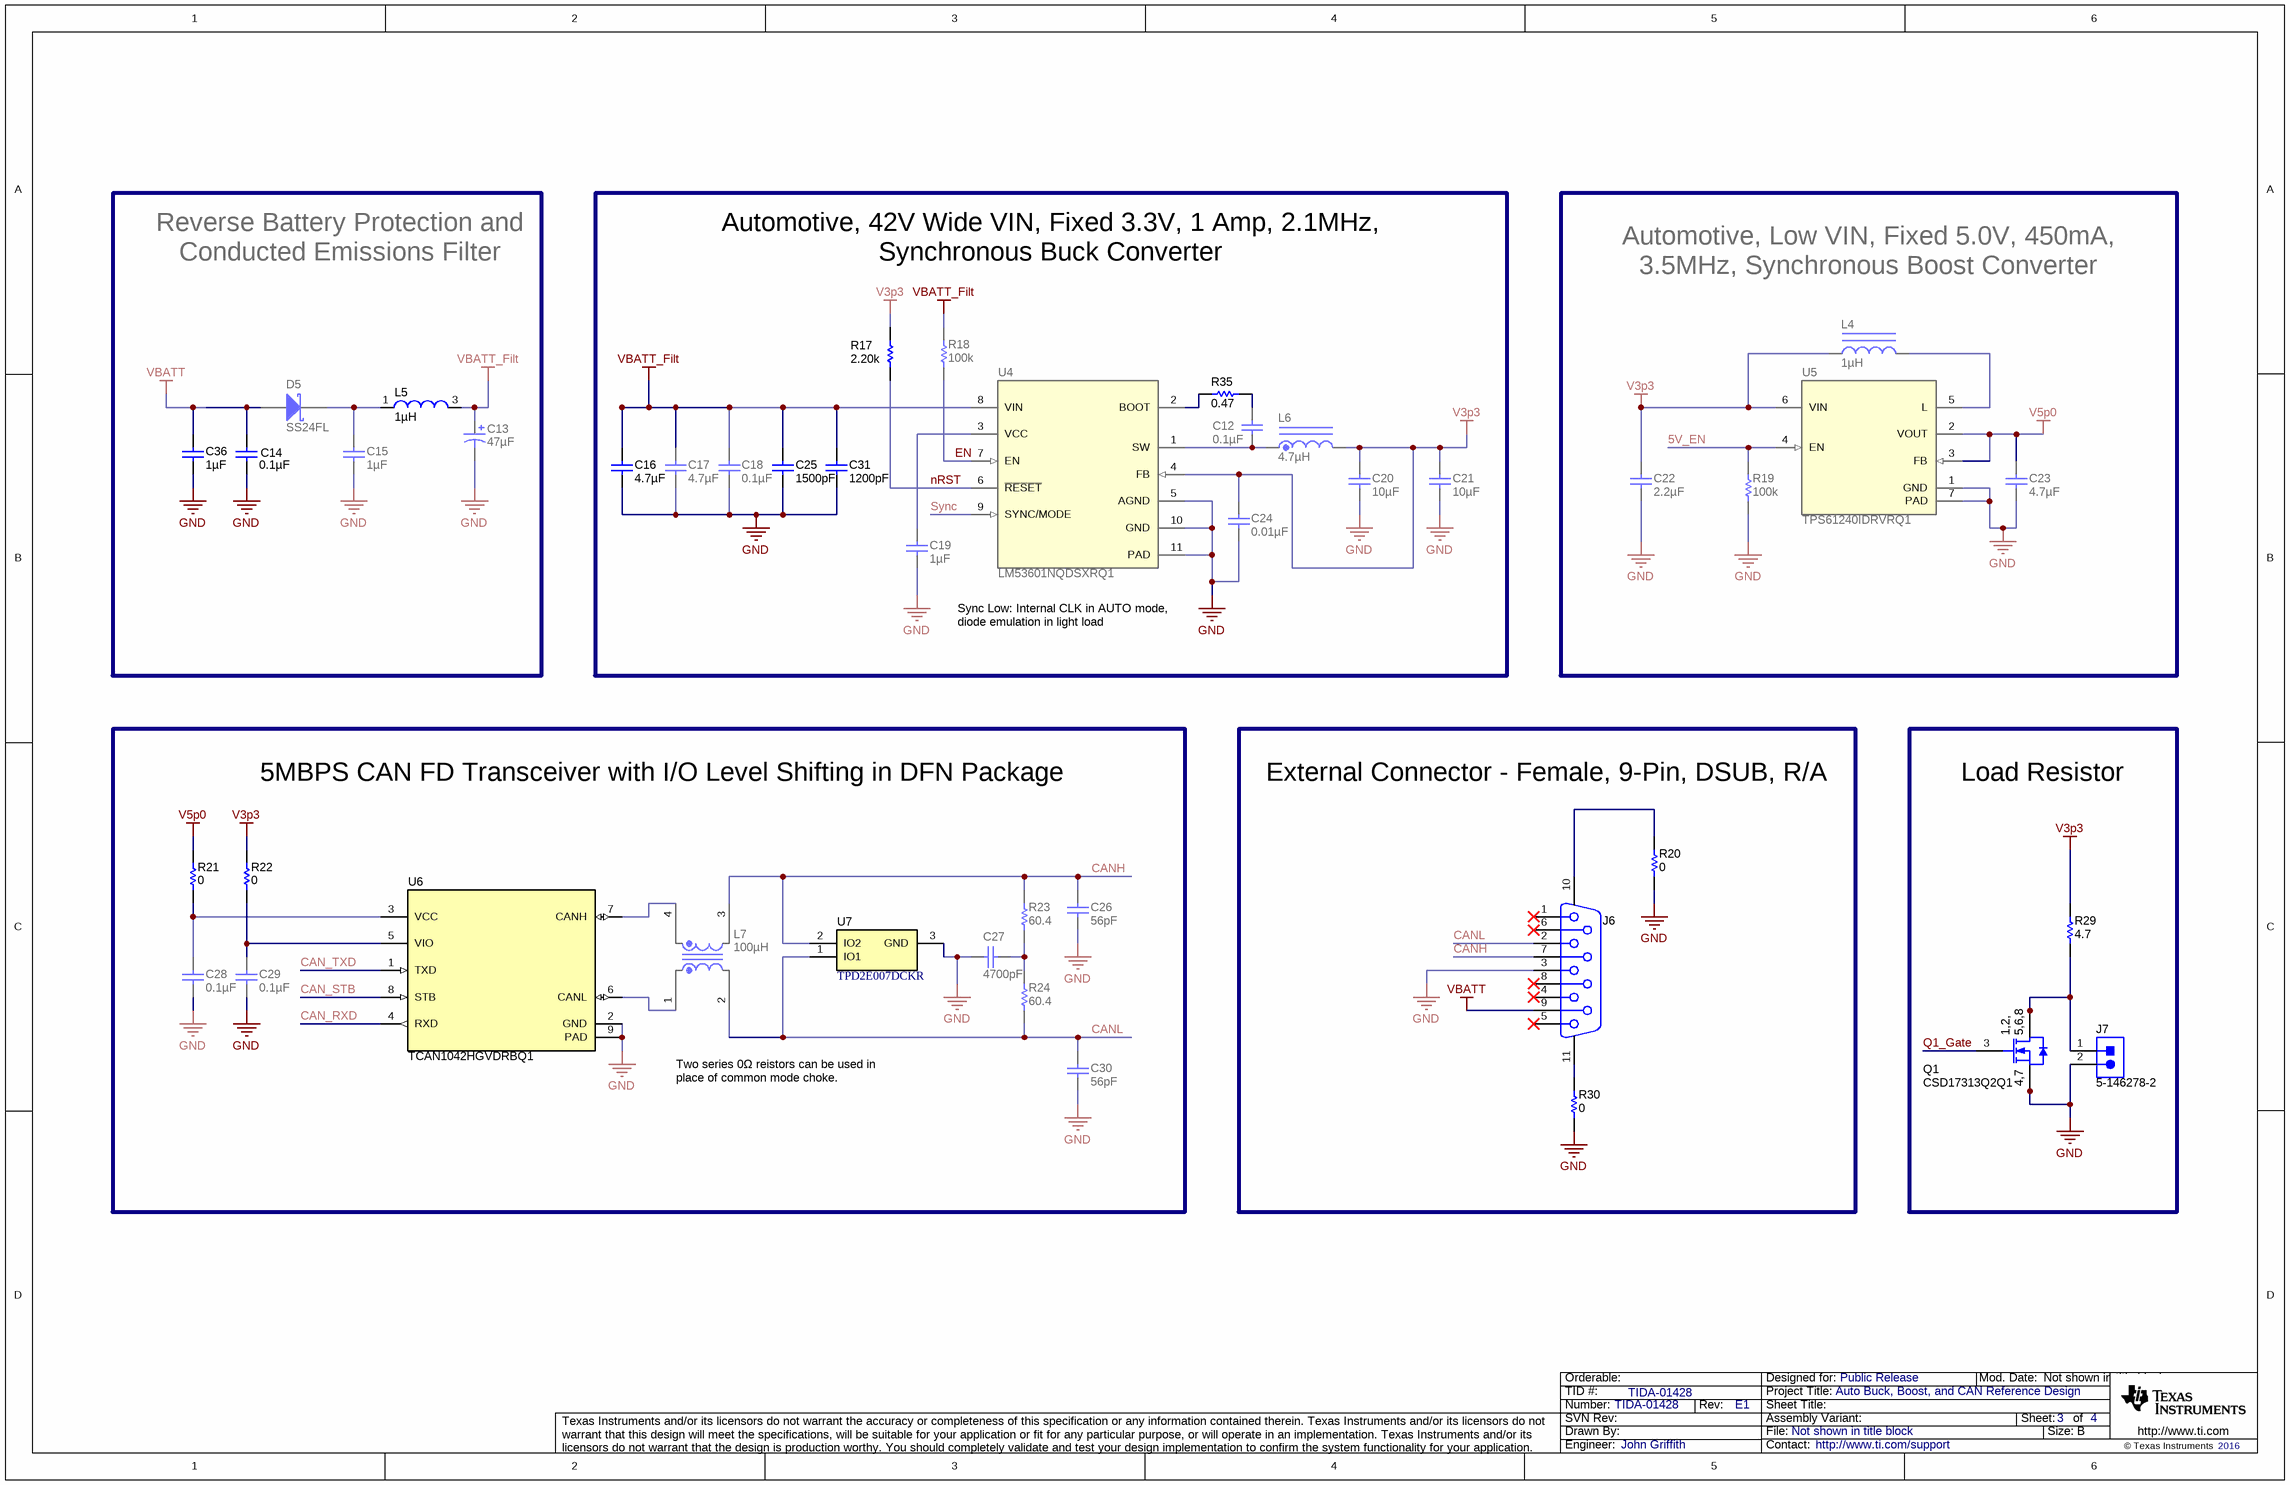
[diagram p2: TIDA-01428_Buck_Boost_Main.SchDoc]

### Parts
C12  ValueDisplayed: 0.1µF  [0603S]  (hidden comment: GCM188R71H104KA57D)
C13  ValueDisplayed: 47µF  [SM_RADIAL_F]  (hidden comment: EEE-FK1J470P)
C14  ValueDisplayed: 0.1µF  [0603S]  (hidden comment: GCJ188R72A104KA01D)
C15  ValueDisplayed: 1µF  [0603]  (hidden comment: GRM188R61H105KAALD)
C16  ValueDisplayed: 4.7µF  [1206_180]  (hidden comment: GRM31CR71H475KA12L)
C17  ValueDisplayed: 4.7µF  [1206_180]  (hidden comment: GRM31CR71H475KA12L)
C18  ValueDisplayed: 0.1µF  [0805_HV]  (hidden comment: C2012X7R2A104K125AA)
C19  ValueDisplayed: 1µF  [0603S]  (hidden comment: GCM188R71C105KA64D)
C20  ValueDisplayed: 10µF  [1206_180]  (hidden comment: GRM31CR71C106KAC7L)
C21  ValueDisplayed: 10µF  [1206_180]  (hidden comment: GRM31CR71C106KAC7L)
C22  ValueDisplayed: 2.2µF  [0603S]  (hidden comment: C0603C225K8PACTU)
C23  ValueDisplayed: 4.7µF  [0603S]  (hidden comment: C0603C475K8PACTU)
C24  ValueDisplayed: 0.01µF  [0402S]  (hidden comment: C1005X7R1C103K050BA)
C25  ValueDisplayed: 1500pF  [0402S]  (hidden comment: CGA2B3X7S2A152K050BB)
C26  ValueDisplayed: 56pF  [0603S]  (hidden comment: GRM1885C1H560JA01D)
C27  ValueDisplayed: 4700pF  [0603S]  (hidden comment: GCM188R71H472KA37D)
C28  ValueDisplayed: 0.1µF  [0603S]  (hidden comment: 06033C104JAT2A)
C29  ValueDisplayed: 0.1µF  [0603S]  (hidden comment: 06033C104JAT2A)
C30  ValueDisplayed: 56pF  [0603S]  (hidden comment: GRM1885C1H560JA01D)
C31  ValueDisplayed: 1200pF  [0402S]  (hidden comment: C0402C122J5GACTU)
C36  ValueDisplayed: 1µF  [0603S]  (hidden comment: UMK107AB7105KA-T)
D5  SS24FL  [SOD-123F]
J6  1734354-1  [TE_1734354-1]  (value not drawn)
J7  5-146278-2  [TE_5-146278-2]
L4  ValueDisplayed: 1µH  [NLCV32]  (hidden comment: NLCV32T-1R0M-PF)
L5  ValueDisplayed: 1µH  [WE-TPC-8015]  (hidden comment: 7440690010)
L6  ValueDisplayed: 4.7µH  [MPI4040R3]  (hidden comment: MPI4040R3-4R7-R)
L7  ValueDisplayed: 100µH  [SIMDAD_1812]  (hidden comment: B82789C0104H001)
Q1  CSD17313Q2Q1  [DQK0006C]
R17  ValueDisplayed: 2.20k  [0603S]  (hidden comment: RC0603FR-072K2L)
R18  ValueDisplayed: 100k  [0603S]  (hidden comment: CRCW0603100KFKEA)
R19  ValueDisplayed: 100k  [0603S]  (hidden comment: CRCW0603100KFKEA)
R20  ValueDisplayed: 0  [0603S]  (hidden comment: ERJ-3GEY0R00V)
R21  ValueDisplayed: 0  [0603S]  (hidden comment: ERJ-3GEY0R00V)
R22  ValueDisplayed: 0  [0603S]  (hidden comment: ERJ-3GEY0R00V)
R23  ValueDisplayed: 60.4  [1206]  (hidden comment: CRCW120660R4FKEA)
R24  ValueDisplayed: 60.4  [1206]  (hidden comment: CRCW120660R4FKEA)
R29  ValueDisplayed: 4.7  [PNP300]  (hidden comment: PNP300JR-73-4R7)
R30  ValueDisplayed: 0  [0603S]  (hidden comment: ERJ-3GEY0R00V)
R35  ValueDisplayed: 0.47  [0402S]  (hidden comment: ERJ-2BQFR47X)
U4  LM53601NQDSXRQ1  [DSX0010A]
U5  TPS61240IDRVRQ1  [DRV0006A]
U6  TCAN1042HGVDRBQ1  [DRB0008F]
U7  TPD2E007DCKR  [DCK0003A_N]

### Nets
GND: C13.2(-) C14.2 C15.2 C16.2 C17.2 C18.2 C19.2 C20.2 C21.2 C22.2 C23.2 C24.2 C25.2 C26.2 C27.2 C28.2 C29.2 C30.2 C31.2 C36.2 J6.3 J7.2 Q1.4(S) Q1.7(S) R19.1 R20.2 R30.2 U4.5(AGND) U4.10(GND) U4.11(PAD) U5.1(GND) U5.7(PAD) U6.2(GND) U6.9(PAD) U7.3(GND)
V3p3: C20.1 C21.1 C22.1 C24.1 L4.1 L6.2 R17.1 R22.1 R29.2 U4.4(FB) U5.6(VIN)
V5p0: C23.1 R21.1 U5.2(VOUT) U5.3(FB)
VBATT: C14.1 C36.1 D5.2(A) J6.9
VBATT_Filt: C13.1(+) C16.1 C17.1 C18.1 C25.1 C31.1 L5.3 R18.2 U4.8(VIN)
5V_EN: R19.2 U5.4(EN)
CAN_RXD: U6.4(RXD)
CAN_STB: U6.8(STB)
CAN_TXD: U6.1(TXD)
CANH: C26.1 J6.7 L7.3 R23.2 U7.2(IO2)
CANL: C30.1 J6.2 L7.2 R24.1 U7.1(IO1)
EN: R18.1 U4.7(EN)
nRST: R17.2 U4.6(~{RESET})
Q1_Gate: Q1.3(G)
Sync: U4.9(SYNC/MODE)
NetC12_1: C12.1 R35.2
NetC12_2: C12.2 L6.1 U4.1(SW)
NetC15_1: C15.1 D5.1(K) L5.1
NetC19_1: C19.1 U4.3(VCC)
NetC27_1: C27.1 R23.1 R24.2
NetC28_1: C28.1 R21.2 U6.3(VCC)
NetC29_1: C29.1 R22.2 U6.5(VIO)
NetJ6_10: J6.10 R20.1
NetJ6_11: J6.11 R30.1
NetJ7_1: J7.1 Q1.1(D) Q1.2(D) Q1.5(D) Q1.6(D) Q1.8(D) R29.1
NetL4_2: L4.2 U5.5(L)
NetL7_1: L7.1 U6.6(CANL)
NetL7_4: L7.4 U6.7(CANH)
NetR35_1: R35.1 U4.2(BOOT)

Not connected (* = marked no-connect by the designer): J6 1* 4* 5* 6* 8*

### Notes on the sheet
- Reverse Battery Protection and Conducted Emissions Filter
- Automotive, 42V Wide VIN, Fixed 3.3V, 1 Amp, 2.1MHz, Synchronous Buck Converter
- Automotive, Low VIN, Fixed 5.0V, 450mA, 3.5MHz, Synchronous Boost Converter
- diode emulation in light load
- Sync Low: Internal CLK in AUTO mode,
- 5MBPS CAN FD Transceiver with I/O Level Shifting in DFN Package
- External Connector - Female, 9-Pin, DSUB, R/A
- Load Resistor
- Two series 0Ω reistors can be used in
- place of common mode choke.

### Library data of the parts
C12 = GCM188R71H104KA57D: CAP, CERM, 0.1 µF, 50 V, +/- 10%, X7R, 0603; Manufacturer: MuRata; Polarized: N; CompType: Capacitor; Value: 0.1uF; U/M: EA; Cap_F: 0.0000001; Tolerance_%: 10; ESR_ohm: 0.02; Value1: 0.02 ohm; VDC_V: 50; Value2: 50V; IRMS_A: 1.84; TaMin_C: -55; TaMax_C: 125; Cap_Case: 0603; SizeArea_mm2: 1.28; SizeAreaWB_mm2: 4.68; SizeX_mm: 1.6; SizeY_mm: 0.8; SizeZ_mm: 1; AEC Category: Q200
C13 = EEE-FK1J470P: CAP, AL, 47 µF, 63 V, +/- 20%, 0.65 ohm, AEC-Q200 Grade 2, SMD; Manufacturer: Panasonic; Polarized: Y; CompType: Capacitor; Value: 47uF; U/M: EA; Cap_F: 0.000047; Tolerance_%: 20; VDC_V: 63; Value2: 63V; ESR_ohm: 0.65; IRMS_A: 0.25; TaMin_C: -55; TaMax_C: 105; Cap_Case: F; SizeAreaWB_mm2: 123.6; SizeArea_mm2: 83; SizeX_mm: 10; SizeY_mm: 8.3; SizeZ_mm: 10.2; AEC Category: Q200; AEC Grade: 2
C14 = GCJ188R72A104KA01D: CAP, CERM, 0.1 µF, 100 V, +/- 10%, X7R, AEC-Q200 Grade 1, 0603; Manufacturer: MuRata; Polarized: N; CompType: Capacitor; Value: 0.1uF; U/M: EA; Cap_F: 0.0000001; Tolerance_%: 10; Value1: Unknown; VDC_V: 100; Value2: 100V; TaMin_C: -55; TaMax_C: 125; Cap_Case: 0603; SizeArea_mm2: 1.28; SizeAreaWB_mm2: 4.68; SizeX_mm: 1.6; SizeY_mm: 0.8; SizeZ_mm: 1; AEC Category: Q200; AEC Qualified: Y
C15 = GRM188R61H105KAALD: CAP, CERM, 1 µF, 50 V, +/- 10%, X5R, 0603; Manufacturer: MuRata; Polarized: N; CompType: Capacitor; Value: 1uF; U/M: EA; Cap_F: 0.000001; Tolerance_%: 10; Value1: Unknown; VDC_V: 50; Value2: 50V; TaMin_C: -55; TaMax_C: 85; SizeArea_mm2: 1.28; SizeAreaWB_mm2: 4.68; SizeX_mm: 1.6; SizeY_mm: 0.8; SizeZ_mm: 1; AEC Category: Q200
C16 C17 = GRM31CR71H475KA12L: CAP, CERM, 4.7 µF, 50 V, +/- 10%, X7R, 1206; Manufacturer: MuRata; Polarized: N; CompType: Capacitor; Value: 4.7uF; U/M: EA; Cap_F: 0.0000047; Tolerance_%: 10; Value1: Unknown; VDC_V: 50; Value2: 50V; TaMin_C: -55; TaMax_C: 125; Cap_Case: 2220; SizeArea_mm2: 5.12; SizeAreaWB_mm2: 10.92; SizeX_mm: 3.2; SizeY_mm: 1.6; SizeZ_mm: 1.8; AEC Category: Q200
C18 = C2012X7R2A104K125AA: CAP, CERM, 0.1 µF, 100 V, +/- 10%, X7R, 0805; Manufacturer: TDK; Polarized: N; CompType: Capacitor; Value: 0.1uF; U/M: EA; Cap_F: 0.0000001; Tolerance_%: 10; ESR_ohm: 0.020726; Value1: 0.020726 ohm; VDC_V: 100; Value2: 100V; IRMS_A: 1.456; TaMin_C: -55; TaMax_C: 125; Cap_Case: 0805; SizeArea_mm2: 2.5; SizeAreaWB_mm2: 6.75; SizeX_mm: 2; SizeY_mm: 1.25; SizeZ_mm: 1.45; AEC Category: Q200
C19 = GCM188R71C105KA64D: CAP, CERM, 1 µF, 16 V, +/- 10%, X7R, AEC-Q200 Grade 1, 0603; Manufacturer: MuRata; Polarized: N; CompType: Capacitor; Value: 1uF; U/M: EA; Cap_F: 0.000001; Tolerance_%: 10; Value1: Unknown; VDC_V: 16; Value2: 16V; TaMin_C: -55; TaMax_C: 125; Cap_Case: 0603; SizeArea_mm2: 1.28; SizeAreaWB_mm2: 4.68; SizeX_mm: 1.6; SizeY_mm: 0.8; SizeZ_mm: 1; AEC Category: Q200; AEC Qualified: Y
C20 C21 = GRM31CR71C106KAC7L: CAP, CERM, 10 µF, 16 V, +/- 10%, X7R, 1206; Manufacturer: MuRata; Polarized: N; CompType: Capacitor; Value: 10uF; U/M: EA; Cap_F: 0.00001; Tolerance_%: 10; Value1: Unknown; VDC_V: 16; Value2: 16V; TaMin_C: -55; TaMax_C: 125; Cap_Case: 1206; SizeArea_mm2: 5.12; SizeAreaWB_mm2: 10.92; SizeX_mm: 3.2; SizeY_mm: 1.6; SizeZ_mm: 1.8; AEC Category: Q200
C22 = C0603C225K8PACTU: CAP, CERM, 2.2 µF, 10 V, +/- 10%, X5R, 0603; Manufacturer: Kemet; Polarized: N; CompType: Capacitor; Value: 2.2uF; U/M: EA; Cap_F: 0.0000022; Tolerance_%: 10; Value1: Unknown; Value2: 10V; TaMin_C: -55; TaMax_C: 85; Cap_Case: 0603; SizeArea_mm2: 1.28; SizeAreaWB_mm2: 4.68; SizeX_mm: 1.6; SizeY_mm: 0.8; SizeZ_mm: 1; AEC Category: Q200
C23 = C0603C475K8PACTU: CAP, CERM, 4.7 µF, 10 V, +/- 10%, X5R, 0603; Manufacturer: Kemet; Polarized: N; CompType: Capacitor; Value: 4.7uF; U/M: EA; Cap_F: 0.0000047; Tolerance_%: 10; ESR_ohm: 0.006; Value1: 0.006 ohm; Value2: 10V; IRMS_A: 7.24; TaMin_C: -55; TaMax_C: 85; Cap_Case: 0603; SizeArea_mm2: 1.28; SizeAreaWB_mm2: 4.68; SizeX_mm: 1.6; SizeY_mm: 0.8; SizeZ_mm: 1; AEC Category: Q200
C24 = C1005X7R1C103K050BA: CAP, CERM, 0.01 µF, 16 V, +/- 10%, X7R, 0402; Manufacturer: TDK; Polarized: N; CompType: Capacitor; Value: 0.01uF; U/M: EA; Cap_F: 0.00000001; Tolerance_%: 10; ESR_ohm: 0.0623; Value1: 0.0623 ohm; VDC_V: 16; Value2: 16V; TaMin_C: -55; TaMax_C: 125; Cap_Case: 0402; SizeArea_mm2: 0.5; SizeAreaWB_mm2: 3; SizeX_mm: 1; SizeZ_mm: 0.6; AEC Category: Q200
C25 = CGA2B3X7S2A152K050BB: CAP, CERM, 1500 pF, 100 V, +/- 10%, X7S, AEC-Q200 Grade 1, 0402; Manufacturer: TDK; Polarized: N; CompType: Capacitor; Value: 1500pF; U/M: EA; Cap_F: 0.0000000015; Tolerance_%: 10; ESR_ohm: 1.89793; Value1: 1.89793 ohm; VDC_V: 100; Value2: 100V; IRMS_A: 0.24508; TaMin_C: -55; TaMax_C: 125; Cap_Case: 0402; SizeArea_mm2: 0.5; SizeAreaWB_mm2: 3; SizeX_mm: 1; SizeZ_mm: 0.6; AEC Category: Q200; AEC Qualified: Y
C26 C30 = GRM1885C1H560JA01D: CAP, CERM, 56 pF, 50 V, +/- 5%, C0G/NP0, 0603; Manufacturer: MuRata; Polarized: N; CompType: Capacitor; Value: 56pF; U/M: EA; Cap_F: 0.000000000056; Tolerance_%: 5; Value1: Unknown; VDC_V: 50; Value2: 50V; TaMin_C: -55; TaMax_C: 125; Cap_Case: 0603; SizeArea_mm2: 1.28; SizeAreaWB_mm2: 4.68; SizeX_mm: 1.6; SizeY_mm: 0.8; SizeZ_mm: 1; AEC Category: Q200
C27 = GCM188R71H472KA37D: CAP, CERM, 4700 pF, 50 V, +/- 10%, X7R, AEC-Q200 Grade 1, 0603; Manufacturer: MuRata; Polarized: N; CompType: Capacitor; Value: 4700pF; U/M: EA; Cap_F: 0.0000000047; Tolerance_%: 10; Value1: Unknown; VDC_V: 50; Value2: 50V; TaMin_C: -55; TaMax_C: 125; Cap_Case: 0603; SizeArea_mm2: 1.28; SizeAreaWB_mm2: 4.68; SizeX_mm: 1.6; SizeY_mm: 0.8; SizeZ_mm: 1; AEC Category: Q200; AEC Qualified: Y
C28 C29 = 06033C104JAT2A: as C2 on sheet TIDA-01428_Buck_Boost_MCU
C31 = C0402C122J5GACTU: CAP, CERM, 1200 pF, 50 V, +/- 5%, C0G/NP0, 0402; Manufacturer: Kemet; Polarized: N; CompType: Capacitor; Value: 1200pF; U/M: EA; Cap_F: 0.0000000012; Tolerance_%: 5; Value1: Unknown; VDC_V: 50; Value2: 50V; TaMin_C: -55; TaMax_C: 125; Cap_Case: 0402; SizeArea_mm2: 0.5; SizeAreaWB_mm2: 3; SizeX_mm: 1; SizeZ_mm: 0.6; AEC Category: Q200; Green_Lifecycle: Not Set; Green_REACh: Incomplete
C36 = UMK107AB7105KA-T: CAP, CERM, 1 µF, 50 V, +/- 10%, X7R, 0603; Manufacturer: Taiyo Yuden; Polarized: N; CompType: Capacitor; Value: 1uF; U/M: EA; Cap_F: 0.000001; Tolerance_%: 10; Value1: Unknown; VDC_V: 50; Value2: 50V; TaMin_C: -55; TaMax_C: 125; Cap_Case: 0603; SizeArea_mm2: 1.28; SizeAreaWB_mm2: 4.68; SizeX_mm: 1.6; SizeY_mm: 0.8; SizeZ_mm: 1; AEC Category: Q200
D5 = SS24FL: Diode, Schottky, 40 V, 2 A, AEC-Q101, SOD-123F; Manufacturer: Fairchild Semiconductor; U/M: EA; Vf_V: 0.55; Value: 40V; Value1: 2A; Value2: 0.55V; Io_A: 2; Vr_V: 40; TJmax_C: 125; SizeAreaWB_mm2: 11.7; SizeArea_mm2: 5.6; SizeX_mm: 3.5; SizeY_mm: 1.6; SizeZ_mm: 1.1; AEC Category: Q101; AEC Qualified: Y
J6 = 1734354-1: Receptacle, D-Sub, 9 Position, R/A, TH; Manufacturer: TE Connectivity; SymbolCreator: Altium; Gender: Female; ContactFinish: Gold
J7 = 5-146278-2: Header, 100mil, 2x1, Tin, TH; Manufacturer: TE Connectivity; SymbolCreator: a0412235
L4 = NLCV32T-1R0M-PF: Inductor, Wirewound, Ferrite, 1 µH, 1 A, 0.06 ohm, SMD; Manufacturer: TDK; Value: 1uH; Ind_H: 1.0E-6; Imax_A: 1; Irms: 1A @ 20C rise; Isat: 1A @ 10% inductance drop; DCR_ohm: 0.06; Value2: 1A; SizeAreaWB_mm2: 13.44; SizeArea_mm2: 7.04; SizeX_mm: 3.2; SizeY_mm: 2.2; SizeZ_mm: 2.5; AEC Category: Q200
L5 = 7440690010: Inductor, Shielded Drum Core, Ferrite, 1 µH, 3.6 A, 0.026 ohm, SMD; Manufacturer: Wurth Elektronik; SymbolCreator: a0411947; Ind_H: 1.0E-6; Value: 1uH; Imax_A: 3.6; Irms: 3.6A @ 40C rise; Isat: 3.8A @ 35% inductance drop; DCR_ohm: 0.026; Value2: 3.6A; SizeAreaWB_mm2: 100; SizeArea_mm2: 64; SizeX_mm: 8; SizeZ_mm: 1.35; AEC Category: Q200
L6 = MPI4040R3-4R7-R: Inductor, Shielded, 4.7 µH, 2.3 A, 0.092 ohm, SMD; Manufacturer: Coiltronics; Value: 4.7uH; SymbolCreator: a0412235; Ind_H: 4.7E-6; Imax_A: 2.3; Irms: 2.3A @ 40C rise; Isat: 4.8A @ 30% inductance drop; DCR_ohm: 0.092; Value2: 2.3A; SizeAreaWB_mm2: 27.577; SizeArea_mm2: 18.067; SizeX_mm: 4.45; SizeY_mm: 4.06; SizeZ_mm: 1.8; AEC Category: Q200
L7 = B82789C0104H001: Coupled inductor, 100 µH, 0.15 A, 1.5 ohm, SMD; Manufacturer: TDK; SymbolCreator: a0412235; Value: 100uH; Ind_H: 100.0E-6; DCR_ohm: 1.5
Q1 = CSD17313Q2Q1: MOSFET, N-CH, 30 V, 5 A, AEC-Q101, DQK0006C (WSON-6); Manufacturer: Texas Instruments; Alternate Manufacturer: None; U/M: EA; ChType: N; Value: 30V; VdsMax_V: 30; Value1: 0.032 ohm; Rdson45_ohm: 0.032; Value2: 2.1 nC; QgTyp_nC: 2.1; Vgs_V: 10; IdsMax_A: 5; SizeAreaWB_mm2: 9; SizeArea_mm2: 4; SizeX_mm: 2; SizeZ_mm: 0.8; AEC Category: Q101; AEC Qualified: Y
R17 = RC0603FR-072K2L: as R11 on sheet TIDA-01428_Buck_Boost_MCU
R18 R19 = CRCW0603100KFKEA: as R5 on sheet TIDA-01428_Buck_Boost_MCU
R20-R22 R30 = ERJ-3GEY0R00V: RES, 0, 5%, 0.1 W, 0603; Manufacturer: Panasonic; CompType: Resistor; Value: 0; Value_Code: 0000; Tolerance_%: 5; Power_W: 0.1; Value2: 0.1W; VDC_V: 50; TempCo: 600 ppm/C; SizeArea_mm2: 1.28; SizeX_mm: 1.6; SizeY_mm: 0.8; SizeZ_mm: 1; EIA_Code: E24; U/M: EA; AEC Category: Q200
R23 R24 = CRCW120660R4FKEA: RES, 60.4, 1%, 0.25 W, 1206; Manufacturer: Vishay-Dale; CompType: Resistor; Value: 60.4; Value_Code: 60R4; Tolerance_%: 1; Power_W: 0.25; Value2: 0.25W; VDC_V: 200; TempCo: 100 ppm/C; SizeArea_mm2: 5.12; SizeX_mm: 3.2; SizeY_mm: 1.6; SizeZ_mm: 1.35; EIA_Code: E96; U/M: EA; AEC Category: Q200
R29 = PNP300JR-73-4R7: RES, 4.7, 5%, 3 W, 3W Axial resistor; Manufacturer: Yageo America; Value: 4.7; Value_Code: 4R70; Tolerance_%: 5; Power_W: 3; TempCo: 300 ppm/C; EIA_Code: E24; U/M: EA; AEC Category: Q200; AEC Qualified: N
R35 = ERJ-2BQFR47X: RES, 0.47, 1%, 0.125 W, 0402; Manufacturer: Panasonic; CompType: Resistor; Value: 0.47; Value_Code: R470; Tolerance_%: 1; Power_W: 0.125; Value2: 0.125W; TempCo: 250 ppm/C; SizeArea_mm2: 0.5; SizeZ_mm: 0.6; EIA_Code: E96; U/M: EA; AEC Category: Q200
U4 = LM53601NQDSXRQ1: 3.5V to 36V, 1A Synchronous 2.1MHz Step-Down Converter for Automotive Applications, DSX0010A (WSON-10); Manufacturer: Texas Instruments; SymbolCreator: Altium; SizeArea_mm2: 9; SizeAreaWB_mm2: 16; SizeX_mm: 3; SizeZ_mm: 0.8; CompType: IC; U/M: EA
U5 = TPS61240IDRVRQ1: Automotive Catalog 5V, 400mA, 4MHz Step-Up DC/DC Converter, DRV0006A (WSON-6); Manufacturer: Texas Instruments; SymbolCreator: a799628; SizeArea_mm2: 4; SizeAreaWB_mm2: 9; SizeX_mm: 2; SizeZ_mm: 0.8; CompType: IC; U/M: EA
U6 = TCAN1042HGVDRBQ1: Automotive Fault Protected CAN Transceiver With Flexible Data-Rate, DRB0008F (VSON-8); Manufacturer: Texas Instruments; SymbolCreator: a0411947; SizeArea_mm2: 9; SizeAreaWB_mm2: 16; SizeX_mm: 3; SizeZ_mm: 1; CompType: IC; U/M: EA
U7 = TPD2E007DCKR: ESD Protection Array for AC Signal Data Interface, 2 Channels, -40 to +85 degC, 3-pin SC70 (DCK), Green (RoHS & no Sb/Br); Manufacturer: Texas Instruments; Alternate PartNumber: Equivalent; Breakdown Voltage(Min)(V): +/-14; IEC 61000-4-2 Air-Gap(+/- kV): 15; IEC 61000-4-2 Contact(+/- kV): 8; IO Leakage Current(nA): 50; SubFamily: ESD Solution

## Sheet TIDA-01428_Buck_Boost_Hardware.SchDoc
size 431 x 279 mm; Date: Not shown in title block; ApprovedBy: Not shown in title block; CheckedBy: Not shown in title block; Author: Not shown in title block; CompanyName: Not shown in title block; Engineer: Not shown in title block; Organization: Not shown in title block; Address1: Not shown in title block; Address2: Not shown in title block; Address3: Not shown in title block; Address4: Not shown in title block; DocumentNumber: 4; Revision: Use project parameter SCH_Rev; SheetNumber: 4; SheetTotal: 4; PageSetup: Record=PageOptions¦CenterHorizontal=True¦CenterVertical=True¦PrintScale=1.00¦XCorrection=1.00¦YCorrection=1.00¦PrintKind=0¦BorderSize=5000000¦LeftOffset=0¦BottomOffset=0¦Orientation=2¦PaperLength=1000¦PaperWidth=1000¦Scale=100¦PaperSource=15¦PrintQuality=600¦MediaType=1¦DitherType=10¦PaperKind=Letter¦PrintScaleMode=1
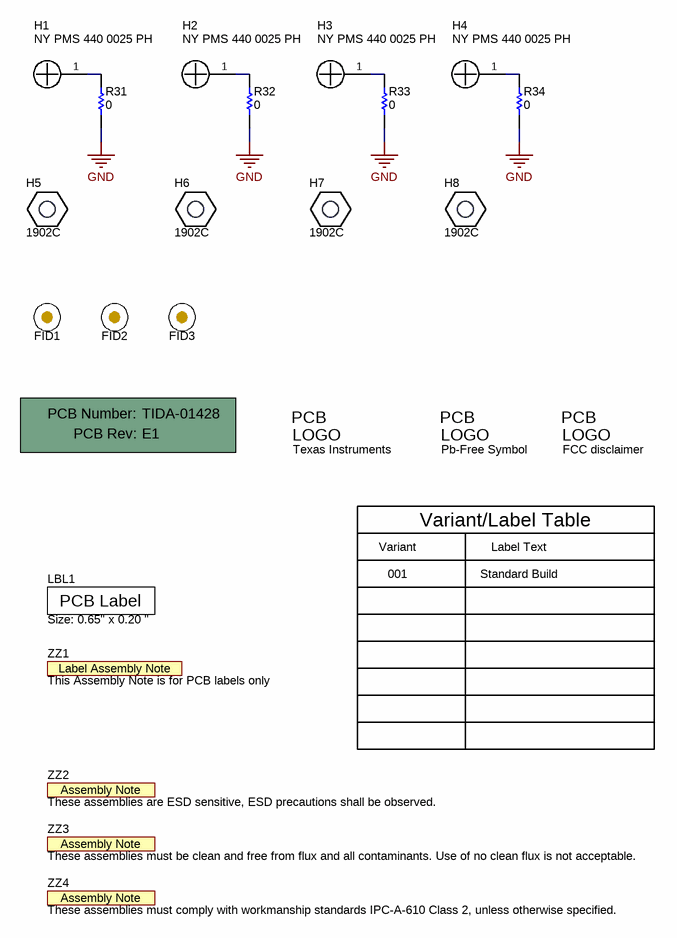
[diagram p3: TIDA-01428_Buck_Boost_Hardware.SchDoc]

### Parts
!PCB1  Printed Circuit Board  (value not drawn)  (mechanical)
FID1  Fiducial  [Fiducial10-20]  (value not drawn)
FID2  Fiducial  [Fiducial10-20]  (value not drawn)
FID3  Fiducial  [Fiducial10-20]  (value not drawn)
H1  NY PMS 440 0025 PH  [NY PMS 440 0025 PH]
H2  NY PMS 440 0025 PH  [NY PMS 440 0025 PH]
H3  NY PMS 440 0025 PH  [NY PMS 440 0025 PH]
H4  NY PMS 440 0025 PH  [NY PMS 440 0025 PH]
H5  1902C  [Keystone_1902C]
H6  1902C  [Keystone_1902C]
H7  1902C  [Keystone_1902C]
H8  1902C  [Keystone_1902C]
LBL1  Size: 0.65" x 0.20 "  [Label_650x200]
Logo1  Texas Instruments  [TI_Stacked_Overlay_Small]  (no BOM)
Logo2  Pb-Free Symbol  [Pb-Free_Overlay_Small]  (no BOM)
Logo3  FCC disclaimer  [FCC_disclaimer]  (no BOM)
R31  ValueDisplayed: 0  [0603S]  (hidden comment: ERJ-3GEY0R00V)
R32  ValueDisplayed: 0  [0603S]  (hidden comment: ERJ-3GEY0R00V)
R33  ValueDisplayed: 0  [0603S]  (hidden comment: ERJ-3GEY0R00V)
R34  ValueDisplayed: 0  [0603S]  (hidden comment: ERJ-3GEY0R00V)
ZZ1  This Assembly Note is for PCB labels only  [AssemblyNoteLabel]  (no BOM)
ZZ2  These assemblies are ESD sensitive, ESD precautions shall be observed.  [AssemblyNote]  (no BOM)
ZZ3  These assemblies must be clean and free from flux and all contaminants. Use of no clean flux is not acceptable.  [AssemblyNote]  (no BOM)
ZZ4  These assemblies must comply with workmanship standards IPC-A-610 Class 2, unless otherwise specified.  [AssemblyNote]  (no BOM)

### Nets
GND: R31.2 R32.2 R33.2 R34.2
NetH1_1: H1.1 R31.1
NetH2_1: H2.1 R32.1
NetH3_1: H3.1 R33.1
NetH4_1: H4.1 R34.1

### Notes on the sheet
- Variant
- Variant/Label Table
- Label Text
- 001
- Standard Build

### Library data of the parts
!PCB1 = PCB: Manufacturer: Any; PartNumber: TIDA-01428; SymbolCreator: a0412235
FID1-FID3 = Fiducial: Fiducial mark.  There is nothing to buy or mount.; SymbolCreator: codlsc
H1-H4 = NY PMS 440 0025 PH: Machine Screw, Round, #4-40 x 1/4, Nylon, Philips panhead; Manufacturer: B&F Fastener Supply; CompType: Hardware; SymbolCreator: codlsc; U/M: EA
H5-H8 = 1902C: Standoff, Hex, 0.5"L #4-40 Nylon; Manufacturer: Keystone; CompType: Hardware
LBL1 = THT-14-423-10: Thermal Transfer Printable Labels, 0.650" W x 0.200" H - 10,000 per roll; Manufacturer: Brady; SymbolCreator: a0412235; CompType: Label
Logo1 = TI_Logo: Texas Instrument Corporate Signature; SymbolCreator: codlsc
Logo2 = Pb-Free: SymbolCreator: a0412235
Logo3 = FCC_disclaimer: SymbolCreator: codlsc
R31-R34 = ERJ-3GEY0R00V: as R20 on sheet TIDA-01428_Buck_Boost_Main
ZZ1 = AssemblyNoteLabel: SymbolCreator: a0412235
ZZ2-ZZ4 = AssemblyNote: SymbolCreator: codlsc

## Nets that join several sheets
GND: TIDA-01428_Buck_Boost_MCU (38 pins), TIDA-01428_Buck_Boost_Main (35 pins), TIDA-01428_Buck_Boost_Hardware (R31.2 R32.2 R33.2 R34.2)
V3p3: TIDA-01428_Buck_Boost_MCU (22 pins), TIDA-01428_Buck_Boost_Main (11 pins)
5V_EN: TIDA-01428_Buck_Boost_MCU (TP1.1 U1.35), TIDA-01428_Buck_Boost_Main (R19.2 U5.4)
CAN_RXD: TIDA-01428_Buck_Boost_MCU (TP5.1 U1.26), TIDA-01428_Buck_Boost_Main (U6.4)
CAN_STB: TIDA-01428_Buck_Boost_MCU (TP2.1 U1.34), TIDA-01428_Buck_Boost_Main (U6.8)
CAN_TXD: TIDA-01428_Buck_Boost_MCU (TP6.1 U1.25), TIDA-01428_Buck_Boost_Main (U6.1)
nRST: TIDA-01428_Buck_Boost_MCU (C37.1 S1.1 TP9.1 U1.7), TIDA-01428_Buck_Boost_Main (R17.2 U4.6)
Q1_Gate: TIDA-01428_Buck_Boost_MCU (U1.64), TIDA-01428_Buck_Boost_Main (Q1.3)
Sync: TIDA-01428_Buck_Boost_MCU (U1.33), TIDA-01428_Buck_Boost_Main (U4.9)

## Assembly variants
001: not fitted C13 FID1 FID2 FID3 U7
